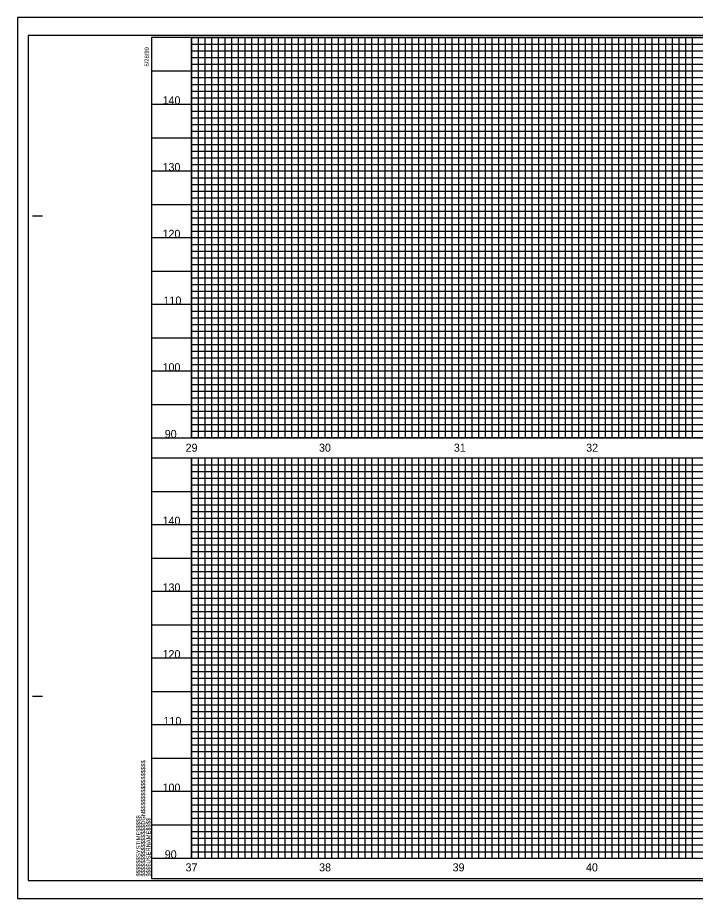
# Model space of a CAD drawing. Extents: x 2113763 to 2114783, y 714280 to 714940.
# Drawn here: x 2113763 to 2114270, y 714280 to 714940 of the extents above; entities that cross this region are included whole.
import ezdxf

# ---------------------------------------------------------------- set-up
doc = ezdxf.new("R2010")
doc.units = 0
for name, color, linetype in [('Exist Vertical Profile Horizontal Axis Label Major', 7, 'Continuous'), ('Exist Vertical Profile Vertical Axis Label', 7, 'Continuous'), ('Sheet Cutting Line CELL', 7, 'Continuous'), ('Sheet Layout Profile Border Port 1', 7, 'Continuous'), ('Sheet Layout Profile Border Port 2', 7, 'Continuous'), ('Sheet Plot Border Inside CELL', 7, 'Continuous'), ('Sheet Plot Border Outside CELL', 7, 'Continuous'), ('Sheet Profile CELL', 7, 'Continuous'), ('Sheet Profile Grid Major CELL', 7, 'Continuous'), ('Sheet Profile Grid Middle CELL', 7, 'Continuous'), ('Sheet Profile Grid Minor CELL', 7, 'Continuous')]:
    doc.layers.add(name, color=color, linetype=linetype)

msp = doc.modelspace()

# ---------------------------------------------------------------- linework, layer by layer
at = {"layer": 'Sheet Cutting Line CELL'}
for p, q in [((2114782.56, 714940.29), (2113762.56, 714940.29)), ((2113762.56, 714940.29), (2113762.56, 714280.29)), ((2113762.56, 714280.29), (2114782.56, 714280.29))]:
    msp.add_line(p, q, dxfattribs=at)
at = {"layer": 'Sheet Layout Profile Border Port 1'}
msp.add_lwpolyline([(2113892.76, 714925.29), (2114642.73, 714925.29), (2114642.73, 714805.41), (2114732.76, 714805.29), (2114732.76, 714625.29), (2113892.76, 714625.29)], close=True, dxfattribs=at)
at = {"layer": 'Sheet Layout Profile Border Port 2'}
msp.add_lwpolyline([(2113892.76, 714610.29), (2114732.76, 714610.29), (2114732.76, 714310.29), (2113892.76, 714310.29)], close=True, dxfattribs=at)
at = {"layer": 'Sheet Plot Border Inside CELL'}
msp.add_lwpolyline([(2113770.36, 714293.76), (2114770.26, 714293.76), (2114770.26, 714926.82), (2113770.36, 714926.82)], close=True, dxfattribs=at)
at = {"layer": 'Sheet Plot Border Outside CELL'}
msp.add_lwpolyline([(2113762.56, 714280.29), (2114782.56, 714280.29), (2114782.56, 714940.29), (2113762.56, 714940.29)], close=True, dxfattribs=at)
at = {"layer": 'Sheet Profile CELL'}
for p, q in [((2113773.66, 714791.79), (2113781.16, 714791.79)), ((2113862.76, 714625.29), (2114762.76, 714625.29)), ((2113862.76, 714610.29), (2114762.76, 714610.29)), ((2113773.66, 714431.79), (2113781.16, 714431.79)), ((2114762.76, 714310.29), (2113862.76, 714310.29)), ((2113862.76, 714295.29), (2114762.76, 714295.29)), ((2113862.76, 714295.29), (2113862.76, 714295.29)), ((2113862.76, 714295.29), (2113862.76, 714295.29)), ((2113862.76, 714295.29), (2113862.76, 714295.29)), ((2113862.76, 714295.29), (2113862.76, 714295.29)), ((2113862.76, 714295.29), (2113862.76, 714295.29)), ((2113862.76, 714295.29), (2113862.76, 714295.29)), ((2113862.76, 714295.29), (2113862.76, 714295.29))]:
    msp.add_line(p, q, dxfattribs=at)
msp.add_lwpolyline([(2114762.76, 714925.29), (2113862.76, 714925.29), (2113862.76, 714295.29), (2114762.76, 714295.29)], close=True, dxfattribs=at)
msp.add_lwpolyline([(2113885.26, 714295.29), (2113885.26, 714295.29)], dxfattribs=at)
at = {"layer": 'Sheet Profile Grid Major CELL'}
for p, q in [((2113892.76, 714925.29), (2113892.76, 714625.29)), ((2113917.76, 714925.29), (2113917.76, 714625.29)), ((2113942.76, 714925.29), (2113942.76, 714625.29)), ((2113967.76, 714925.29), (2113967.76, 714625.29)), ((2113992.76, 714925.29), (2113992.76, 714625.29)), ((2114017.76, 714925.29), (2114017.76, 714625.29)), ((2114042.76, 714925.29), (2114042.76, 714625.29)), ((2114067.76, 714925.29), (2114067.76, 714625.29)), ((2114092.76, 714925.29), (2114092.76, 714625.29)), ((2114117.76, 714925.29), (2114117.76, 714625.29)), ((2114142.76, 714925.29), (2114142.76, 714625.29)), ((2114167.76, 714925.29), (2114167.76, 714625.29)), ((2114192.76, 714925.29), (2114192.76, 714625.29)), ((2114217.76, 714925.29), (2114217.76, 714625.29)), ((2114242.76, 714925.29), (2114242.76, 714625.29)), ((2114267.76, 714925.29), (2114267.76, 714625.29)), ((2113862.76, 714900.29), (2114642.76, 714900.29)), ((2114642.76, 714875.29), (2113862.76, 714875.29)), ((2113862.76, 714850.29), (2114642.76, 714850.29)), ((2114642.76, 714825.29), (2113862.76, 714825.29)), ((2113862.76, 714800.29), (2114762.76, 714800.29)), ((2114762.76, 714775.29), (2113862.76, 714775.29)), ((2113862.76, 714750.29), (2114762.76, 714750.29)), ((2114762.76, 714725.29), (2113862.76, 714725.29)), ((2113862.76, 714700.29), (2114762.76, 714700.29)), ((2114762.76, 714675.29), (2113862.76, 714675.29)), ((2113862.76, 714650.29), (2114762.76, 714650.29)), ((2113892.76, 714610.29), (2113892.76, 714310.29)), ((2113917.76, 714610.29), (2113917.76, 714310.29)), ((2113942.76, 714610.29), (2113942.76, 714310.29)), ((2113967.76, 714610.29), (2113967.76, 714310.29)), ((2113992.76, 714610.29), (2113992.76, 714310.29)), ((2114017.76, 714610.29), (2114017.76, 714310.29)), ((2114042.76, 714610.29), (2114042.76, 714310.29)), ((2114067.76, 714610.29), (2114067.76, 714310.29)), ((2114092.76, 714610.29), (2114092.76, 714310.29)), ((2114117.76, 714610.29), (2114117.76, 714310.29)), ((2114142.76, 714610.29), (2114142.76, 714310.29)), ((2114167.76, 714610.29), (2114167.76, 714310.29)), ((2114192.76, 714610.29), (2114192.76, 714310.29)), ((2114217.76, 714610.29), (2114217.76, 714310.29)), ((2114242.76, 714610.29), (2114242.76, 714310.29)), ((2114267.76, 714610.29), (2114267.76, 714310.29)), ((2113862.76, 714585.29), (2114762.76, 714585.29)), ((2114762.76, 714560.29), (2113862.76, 714560.29)), ((2113862.76, 714535.29), (2114762.76, 714535.29)), ((2114762.76, 714510.29), (2113862.76, 714510.29)), ((2113862.76, 714485.29), (2114762.76, 714485.29)), ((2114762.76, 714460.29), (2113862.76, 714460.29)), ((2113862.76, 714435.29), (2114762.76, 714435.29)), ((2114762.76, 714410.29), (2113862.76, 714410.29)), ((2113862.76, 714385.29), (2114762.76, 714385.29)), ((2114762.76, 714360.29), (2113862.76, 714360.29)), ((2113862.76, 714335.29), (2114762.76, 714335.29))]:
    msp.add_line(p, q, dxfattribs=at)
at = {"layer": 'Sheet Profile Grid Middle CELL'}
for p, q in [((2113892.76, 714920.29), (2114642.76, 714920.29)), ((2113892.76, 714915.29), (2114642.76, 714915.29)), ((2113892.76, 714910.29), (2114642.76, 714910.29)), ((2113892.76, 714905.29), (2114642.76, 714905.29)), ((2113892.76, 714895.29), (2114642.76, 714895.29)), ((2113892.76, 714890.29), (2114642.76, 714890.29)), ((2113892.76, 714885.29), (2114642.76, 714885.29)), ((2113892.76, 714880.29), (2114642.76, 714880.29)), ((2113892.76, 714870.29), (2114642.76, 714870.29)), ((2113892.76, 714865.29), (2114642.76, 714865.29)), ((2113892.76, 714860.29), (2114642.76, 714860.29)), ((2113892.76, 714855.29), (2114642.76, 714855.29)), ((2113892.76, 714845.29), (2114642.76, 714845.29)), ((2113892.76, 714840.29), (2114642.76, 714840.29)), ((2113892.76, 714835.29), (2114642.76, 714835.29)), ((2113892.76, 714830.29), (2114642.76, 714830.29)), ((2113892.76, 714820.29), (2114642.76, 714820.29)), ((2113892.76, 714815.29), (2114642.76, 714815.29)), ((2113892.76, 714810.29), (2114642.76, 714810.29)), ((2113892.76, 714805.29), (2114732.76, 714805.29)), ((2113892.76, 714795.29), (2114732.76, 714795.29)), ((2113892.76, 714790.29), (2114732.76, 714790.29)), ((2113892.76, 714785.29), (2114732.76, 714785.29)), ((2113892.76, 714780.29), (2114732.76, 714780.29)), ((2113892.76, 714770.29), (2114732.76, 714770.29)), ((2113892.76, 714765.29), (2114732.76, 714765.29)), ((2113892.76, 714760.29), (2114732.76, 714760.29)), ((2113892.76, 714755.29), (2114732.76, 714755.29)), ((2113892.76, 714745.29), (2114732.76, 714745.29)), ((2113892.76, 714740.29), (2114732.76, 714740.29)), ((2113892.76, 714735.29), (2114732.76, 714735.29)), ((2113892.76, 714730.29), (2114732.76, 714730.29)), ((2113892.76, 714720.29), (2114732.76, 714720.29)), ((2113892.76, 714715.29), (2114732.76, 714715.29)), ((2113892.76, 714710.29), (2114732.76, 714710.29)), ((2113892.76, 714705.29), (2114732.76, 714705.29)), ((2113892.76, 714695.29), (2114732.76, 714695.29)), ((2113892.76, 714690.29), (2114732.76, 714690.29)), ((2113892.76, 714685.29), (2114732.76, 714685.29)), ((2113892.76, 714680.29), (2114732.76, 714680.29)), ((2113892.76, 714670.29), (2114732.76, 714670.29)), ((2113892.76, 714665.29), (2114732.76, 714665.29)), ((2113892.76, 714660.29), (2114732.76, 714660.29)), ((2113892.76, 714655.29), (2114732.76, 714655.29)), ((2113892.76, 714645.29), (2114732.76, 714645.29)), ((2113892.76, 714640.29), (2114732.76, 714640.29)), ((2113892.76, 714635.29), (2114732.76, 714635.29)), ((2113892.76, 714630.29), (2114732.76, 714630.29)), ((2113892.76, 714605.29), (2114732.76, 714605.29)), ((2113892.76, 714600.29), (2114732.76, 714600.29)), ((2113892.76, 714595.29), (2114732.76, 714595.29)), ((2113892.76, 714590.29), (2114732.76, 714590.29)), ((2113892.76, 714580.29), (2114732.76, 714580.29)), ((2113892.76, 714575.29), (2114732.76, 714575.29)), ((2113892.76, 714570.29), (2114732.76, 714570.29)), ((2113892.76, 714565.29), (2114732.76, 714565.29)), ((2113892.76, 714555.29), (2114732.76, 714555.29)), ((2113892.76, 714550.29), (2114732.76, 714550.29)), ((2113892.76, 714545.29), (2114732.76, 714545.29)), ((2113892.76, 714540.29), (2114732.76, 714540.29)), ((2113892.76, 714530.29), (2114732.76, 714530.29)), ((2113892.76, 714525.29), (2114732.76, 714525.29)), ((2113892.76, 714520.29), (2114732.76, 714520.29)), ((2113892.76, 714515.29), (2114732.76, 714515.29)), ((2113892.76, 714505.29), (2114732.76, 714505.29)), ((2113892.76, 714500.29), (2114732.76, 714500.29)), ((2113892.76, 714495.29), (2114732.76, 714495.29)), ((2113892.76, 714490.29), (2114732.76, 714490.29)), ((2113892.76, 714480.29), (2114732.76, 714480.29)), ((2113892.76, 714475.29), (2114732.76, 714475.29)), ((2113892.76, 714470.29), (2114732.76, 714470.29)), ((2113892.76, 714465.29), (2114732.76, 714465.29)), ((2113892.76, 714455.29), (2114732.76, 714455.29)), ((2113892.76, 714450.29), (2114732.76, 714450.29)), ((2113892.76, 714445.29), (2114732.76, 714445.29)), ((2113892.76, 714440.29), (2114732.76, 714440.29)), ((2113892.76, 714430.29), (2114732.76, 714430.29)), ((2113892.76, 714425.29), (2114732.76, 714425.29)), ((2113892.76, 714420.29), (2114732.76, 714420.29)), ((2113892.76, 714415.29), (2114732.76, 714415.29)), ((2113892.76, 714405.29), (2114732.76, 714405.29)), ((2113892.76, 714400.29), (2114732.76, 714400.29)), ((2113892.76, 714395.29), (2114732.76, 714395.29)), ((2113892.76, 714390.29), (2114732.76, 714390.29)), ((2113892.76, 714380.29), (2114732.76, 714380.29)), ((2113892.76, 714375.29), (2114732.76, 714375.29)), ((2113892.76, 714370.29), (2114732.76, 714370.29)), ((2113892.76, 714365.29), (2114732.76, 714365.29)), ((2113892.76, 714355.29), (2114732.76, 714355.29)), ((2113892.76, 714350.29), (2114732.76, 714350.29)), ((2113892.76, 714345.29), (2114732.76, 714345.29)), ((2113892.76, 714340.29), (2114732.76, 714340.29)), ((2113892.76, 714330.29), (2114732.76, 714330.29)), ((2113892.76, 714325.29), (2114732.76, 714325.29)), ((2113892.76, 714320.29), (2114732.76, 714320.29)), ((2113892.76, 714315.29), (2114732.76, 714315.29))]:
    msp.add_line(p, q, dxfattribs=at)
at = {"layer": 'Sheet Profile Grid Minor CELL'}
for p, q in [((2113897.76, 714925.29), (2113897.76, 714625.29)), ((2113902.76, 714925.29), (2113902.76, 714625.29)), ((2113907.76, 714925.29), (2113907.76, 714625.29)), ((2113912.76, 714925.29), (2113912.76, 714625.29)), ((2113922.76, 714925.29), (2113922.76, 714625.29)), ((2113927.76, 714925.29), (2113927.76, 714625.29)), ((2113932.76, 714925.29), (2113932.76, 714625.29)), ((2113937.76, 714925.29), (2113937.76, 714625.29)), ((2113947.76, 714925.29), (2113947.76, 714625.29)), ((2113952.76, 714925.29), (2113952.76, 714625.29)), ((2113957.76, 714925.29), (2113957.76, 714625.29)), ((2113962.76, 714925.29), (2113962.76, 714625.29)), ((2113972.76, 714925.29), (2113972.76, 714625.29)), ((2113977.76, 714925.29), (2113977.76, 714625.29)), ((2113982.76, 714925.29), (2113982.76, 714625.29)), ((2113987.76, 714925.29), (2113987.76, 714625.29)), ((2113997.76, 714925.29), (2113997.76, 714625.29)), ((2114002.76, 714925.29), (2114002.76, 714625.29)), ((2114007.76, 714925.29), (2114007.76, 714625.29)), ((2114012.76, 714925.29), (2114012.76, 714625.29)), ((2114022.76, 714925.29), (2114022.76, 714625.29)), ((2114027.76, 714925.29), (2114027.76, 714625.29)), ((2114032.76, 714925.29), (2114032.76, 714625.29)), ((2114037.76, 714925.29), (2114037.76, 714625.29)), ((2114047.76, 714925.29), (2114047.76, 714625.29)), ((2114052.76, 714925.29), (2114052.76, 714625.29)), ((2114057.76, 714925.29), (2114057.76, 714625.29)), ((2114062.76, 714925.29), (2114062.76, 714625.29)), ((2114072.76, 714925.29), (2114072.76, 714625.29)), ((2114077.76, 714925.29), (2114077.76, 714625.29)), ((2114082.76, 714925.29), (2114082.76, 714625.29)), ((2114087.76, 714925.29), (2114087.76, 714625.29)), ((2114097.76, 714925.29), (2114097.76, 714625.29)), ((2114102.76, 714925.29), (2114102.76, 714625.29)), ((2114107.76, 714925.29), (2114107.76, 714625.29)), ((2114112.76, 714925.29), (2114112.76, 714625.29)), ((2114122.76, 714925.29), (2114122.76, 714625.29)), ((2114127.76, 714925.29), (2114127.76, 714625.29)), ((2114132.76, 714925.29), (2114132.76, 714625.29)), ((2114137.76, 714925.29), (2114137.76, 714625.29)), ((2114147.76, 714925.29), (2114147.76, 714625.29)), ((2114152.76, 714925.29), (2114152.76, 714625.29)), ((2114157.76, 714925.29), (2114157.76, 714625.29)), ((2114162.76, 714925.29), (2114162.76, 714625.29)), ((2114172.76, 714925.29), (2114172.76, 714625.29)), ((2114177.76, 714925.29), (2114177.76, 714625.29)), ((2114182.76, 714925.29), (2114182.76, 714625.29)), ((2114187.76, 714925.29), (2114187.76, 714625.29)), ((2114197.76, 714925.29), (2114197.76, 714625.29)), ((2114202.76, 714925.29), (2114202.76, 714625.29)), ((2114207.76, 714925.29), (2114207.76, 714625.29)), ((2114212.76, 714925.29), (2114212.76, 714625.29)), ((2114222.76, 714925.29), (2114222.76, 714625.29)), ((2114227.76, 714925.29), (2114227.76, 714625.29)), ((2114232.76, 714925.29), (2114232.76, 714625.29)), ((2114237.76, 714925.29), (2114237.76, 714625.29)), ((2114247.76, 714925.29), (2114247.76, 714625.29)), ((2114252.76, 714925.29), (2114252.76, 714625.29)), ((2114257.76, 714925.29), (2114257.76, 714625.29)), ((2114262.76, 714925.29), (2114262.76, 714625.29)), ((2113892.76, 714919.29), (2113892.76, 714919.29)), ((2113897.76, 714610.29), (2113897.76, 714310.29)), ((2113902.76, 714610.29), (2113902.76, 714310.29)), ((2113907.76, 714610.29), (2113907.76, 714310.29)), ((2113912.76, 714610.29), (2113912.76, 714310.29)), ((2113922.76, 714610.29), (2113922.76, 714310.29)), ((2113927.76, 714610.29), (2113927.76, 714310.29)), ((2113932.76, 714610.29), (2113932.76, 714310.29)), ((2113937.76, 714610.29), (2113937.76, 714310.29)), ((2113947.76, 714610.29), (2113947.76, 714310.29)), ((2113952.76, 714610.29), (2113952.76, 714310.29)), ((2113957.76, 714610.29), (2113957.76, 714310.29)), ((2113962.76, 714610.29), (2113962.76, 714310.29)), ((2113972.76, 714610.29), (2113972.76, 714310.29)), ((2113977.76, 714610.29), (2113977.76, 714310.29)), ((2113982.76, 714610.29), (2113982.76, 714310.29)), ((2113987.76, 714610.29), (2113987.76, 714310.29)), ((2113997.76, 714610.29), (2113997.76, 714310.29)), ((2114002.76, 714610.29), (2114002.76, 714310.29)), ((2114007.76, 714610.29), (2114007.76, 714310.29)), ((2114012.76, 714610.29), (2114012.76, 714310.29)), ((2114022.76, 714610.29), (2114022.76, 714310.29)), ((2114027.76, 714610.29), (2114027.76, 714310.29)), ((2114032.76, 714610.29), (2114032.76, 714310.29)), ((2114037.76, 714610.29), (2114037.76, 714310.29)), ((2114047.76, 714610.29), (2114047.76, 714310.29)), ((2114052.76, 714610.29), (2114052.76, 714310.29)), ((2114057.76, 714610.29), (2114057.76, 714310.29)), ((2114062.76, 714610.29), (2114062.76, 714310.29)), ((2114072.76, 714610.29), (2114072.76, 714310.29)), ((2114077.76, 714610.29), (2114077.76, 714310.29)), ((2114082.76, 714610.29), (2114082.76, 714310.29)), ((2114087.76, 714610.29), (2114087.76, 714310.29)), ((2114097.76, 714610.29), (2114097.76, 714310.29)), ((2114102.76, 714610.29), (2114102.76, 714310.29)), ((2114107.76, 714610.29), (2114107.76, 714310.29)), ((2114112.76, 714610.29), (2114112.76, 714310.29)), ((2114122.76, 714610.29), (2114122.76, 714310.29)), ((2114127.76, 714610.29), (2114127.76, 714310.29)), ((2114132.76, 714610.29), (2114132.76, 714310.29)), ((2114137.76, 714610.29), (2114137.76, 714310.29)), ((2114147.76, 714610.29), (2114147.76, 714310.29)), ((2114152.76, 714610.29), (2114152.76, 714310.29)), ((2114157.76, 714610.29), (2114157.76, 714310.29)), ((2114162.76, 714610.29), (2114162.76, 714310.29)), ((2114172.76, 714610.29), (2114172.76, 714310.29)), ((2114177.76, 714610.29), (2114177.76, 714310.29)), ((2114182.76, 714610.29), (2114182.76, 714310.29)), ((2114187.76, 714610.29), (2114187.76, 714310.29)), ((2114197.76, 714610.29), (2114197.76, 714310.29)), ((2114202.76, 714610.29), (2114202.76, 714310.29)), ((2114207.76, 714610.29), (2114207.76, 714310.29)), ((2114212.76, 714610.29), (2114212.76, 714310.29)), ((2114222.76, 714610.29), (2114222.76, 714310.29)), ((2114227.76, 714610.29), (2114227.76, 714310.29)), ((2114232.76, 714610.29), (2114232.76, 714310.29)), ((2114237.76, 714610.29), (2114237.76, 714310.29)), ((2114247.76, 714610.29), (2114247.76, 714310.29)), ((2114252.76, 714610.29), (2114252.76, 714310.29)), ((2114257.76, 714610.29), (2114257.76, 714310.29)), ((2114262.76, 714610.29), (2114262.76, 714310.29)), ((2113892.76, 714604.29), (2113892.76, 714604.29))]:
    msp.add_line(p, q, dxfattribs=at)

# ---------------------------------------------------------------- texts
at = {"layer": 'Exist Vertical Profile Horizontal Axis Label Major'}
for s, p in [('29', (2113888.4, 714615)), ('29', (2113888.4, 714615)), ('29', (2113888.4, 714615)), ('29', (2113888.4, 714615)), ('30', (2113988.31, 714615)), ('30', (2113988.31, 714615)), ('30', (2113988.31, 714615)), ('30', (2113988.31, 714615)), ('31', (2114089.36, 714615)), ('31', (2114089.36, 714615)), ('31', (2114089.36, 714615)), ('31', (2114089.36, 714615)), ('32', (2114188.48, 714615)), ('32', (2114188.48, 714615)), ('32', (2114188.48, 714615)), ('32', (2114188.48, 714615)), ('37', (2113888.36, 714300.53)), ('38', (2113988.39, 714300.53)), ('39', (2114088.4, 714300.53)), ('40', (2114188.31, 714300.53))]:
    msp.add_text(s, height=6, dxfattribs=at).set_placement(p)
at = {"layer": 'Exist Vertical Profile Vertical Axis Label'}
for s, p in [('140', (2113871.12, 714875.29)), ('130', (2113871.12, 714825.29)), ('130', (2113871.12, 714825.29)), ('130', (2113871.12, 714825.29)), ('130', (2113871.12, 714825.29)), ('130', (2113871.12, 714825.29)), ('120', (2113871.12, 714775.29)), ('120', (2113871.12, 714775.29)), ('120', (2113871.12, 714775.29)), ('120', (2113871.12, 714775.29)), ('120', (2113871.12, 714775.29)), ('110', (2113871.84, 714725.29)), ('110', (2113871.84, 714725.29)), ('110', (2113871.84, 714725.29)), ('110', (2113871.84, 714725.29)), ('110', (2113871.84, 714725.29)), ('100', (2113871.12, 714675.29)), ('100', (2113871.12, 714675.29)), ('100', (2113871.12, 714675.29)), ('100', (2113871.12, 714675.29)), ('100', (2113871.12, 714675.29)), ('90', (2113872.78, 714625.29)), ('90', (2113872.78, 714625.29)), ('90', (2113872.78, 714625.29)), ('90', (2113872.78, 714625.29)), ('90', (2113872.78, 714625.29)), ('140', (2113871.12, 714560.29)), ('130', (2113871.12, 714510.29)), ('120', (2113871.12, 714460.29)), ('110', (2113871.84, 714410.29)), ('100', (2113871.12, 714360.29)), ('90', (2113872.78, 714310.29))]:
    msp.add_text(s, height=6, dxfattribs=at).set_placement(p)
at = {"layer": 'Sheet Profile CELL'}
for s, p in [('5/28/99', (2113860.82, 714903.63)), ('$$$$$$$$$$$$$$$$DGN$$$$$$$$$$$$$$$$', (2113858.18, 714296.71)), ('$$$$$$SYSTIME$$$$$', (2113854.55, 714296.71)), ('$$$$USERNAME$$$$', (2113862.13, 714296.72))]:
    msp.add_text(s, height=3.15, rotation=90, dxfattribs=at).set_placement(p)

doc.saveas('drawing.dxf')
